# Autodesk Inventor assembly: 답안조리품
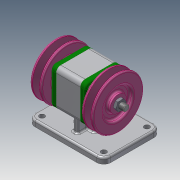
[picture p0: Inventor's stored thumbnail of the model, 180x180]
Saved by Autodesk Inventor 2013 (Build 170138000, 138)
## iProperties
Created: 2020-11
Part Number: 답안조리품
Document SubType Name: Assembly
Designer: user
Author: user
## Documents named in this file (10)
- C:\Users\user\Desktop\701106V1010\답안조리품.iam
- C:\Users\user\Desktop\701106V1010\본체.ipt
- C:\Users\user\Desktop\701106V1010\V-벨트풀리.ipt
- C:\Users\user\Desktop\701106V1010\너트 M10x1.ipt
- C:\Users\user\Desktop\701106V1010\베어링 6004.ipt
- C:\Users\user\Desktop\701106V1010\볼트 M4.ipt
- C:\Users\user\Desktop\701106V1010\오일 실 17 30 5.ipt
- C:\Users\user\Desktop\701106V1010\축.ipt
- C:\Users\user\Desktop\701106V1010\커버.ipt
- C:\Users\user\Desktop\701106V1010\키 5 x 5 x 12.ipt
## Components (2 placed, 1 different names)
1. V-벨트풀리:1
2. V-벨트풀리:2
